Omron CX-Programmer project NuevoProyecto (CX-Programmer 9.50)

# PLC NuevoPLC1: CQM1 CPU21

## Program P1_5 (no task)
Local symbols
B 100.00 BOOL
FSp 15.00 BOOL
p 0.00 BOOL

### Section Sección1_Programa_principal

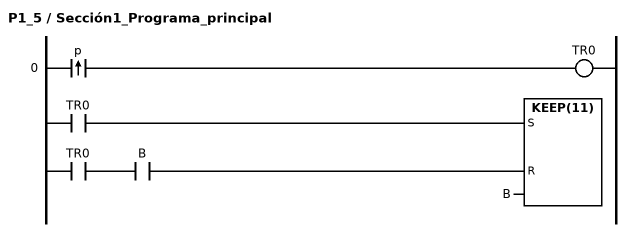
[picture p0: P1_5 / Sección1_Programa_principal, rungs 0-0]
; rung 0
@LD p  // El CQM1 no admite poner p en su forma diferenciada
OUT TR0
LD TR0
LD TR0
AND B
KEEP(11) B

### Section END
; rung 0
END(01)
